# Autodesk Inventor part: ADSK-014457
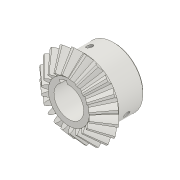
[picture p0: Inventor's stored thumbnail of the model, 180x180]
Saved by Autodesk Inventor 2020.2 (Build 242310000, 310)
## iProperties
CustomPartVersion: 1
Created: 2019-12
Part Number: ADSK-014457
Material: Steel, Mild
Description: Kegelrad1
Document SubType Name: Modeling
Designer: lutzd
Categories: <?xml version="1.0" encoding="UTF-16"?> <MemberInstance><Categories><FamilyTemplate><FamilyTemplateParameter ValueType="xs:double" Id="1" ObjectReferenceKey="da
Mass: 238.264 g
Surface Area: 103.82 cm^2
Volume: 30.3522 cm^3
Density: 7.85 g/cm^3
Appearance: Steel
DocNumber: ADSK-014457
Folder: .
Mass: 0,238 kg
VLT_Material: Stahl, weich
Dimensions: 53,3x33,2x53,3 mm
Title: Kegelrad1
Author: lutzd
Revision Number: -
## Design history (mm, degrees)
node "Oberster Punkt"
node "Netzebene2"
sketch "Skizze des Zahnradkörpers"
  geometry: L1 (0, 0)-(22.879, -27.121); L2 (22.879, -27.121)-(26.768, -23.232); L3 (26.768, -23.232)-(0, 0); L4 (25, -25)-(0, 0); L5 (13.754, -16.305)-(16.093, -13.967); L6 (22.879, -27.121)-(13.754, -16.305); L7 (26.768, -23.232)-(16.093, -13.967); L8 (0, -32.546)-(0, 5.424) reference; L9 (0, -25)-(26.768, -25)
  constraints: 16 end point, 4 point on line, 3 perpendicular, 2 collinear, 1 horizontal alignment, 1 vertical alignment
  dimensions: "d0" = 50 diameter of L4.start L8 (= da_de); "d1" = 45.75736 diameter of L1.end L8 (= da_dfe); "d2" = 53.53553 diameter of L2.end L8 (= da_dae); "d3" = 14.1 distance between parallel lines of L2 L5 (= da_b); "d4" = 23.23223 vertical distance of L2.end L1.start (= da_ve)
revolve "Zahnradkörper" sketch "Skizze des Zahnradkörpers" stored, may be unused: angle "d5" = 90 deg
node "Startpunkt"
node "Zahnebene"
sketch "Startskizze"
  geometry: L1 (0, -43.262)-(0, 12.085) reference; L2 (-1.005, -3.66)-(1.005, -3.66); A1 r 12.943 centre (-13.854, -5.217) between (-1.005, -3.66) and (-4.643, 3.876); A2 r 12.943 centre (13.854, -5.217) between (4.643, 3.876) and (1.005, -3.66); A3 r 39.505 centre (0, -35.355) between (4.643, 3.876) and (-4.643, 3.876); 1 further point
  constraints: 6 point on circle, 3 centre point, 3 symmetric about line, 2 end point, 1 coincident, 1 perpendicular, 1 other
  dimensions: "d7" = 12.94316 radius of A1 (= fd_rr); "d8" = 13.85371 horizontal distance of point (0, -35.355) A1.centre (= fd_x); "d9" = 30.13805 vertical distance of point (0, -35.355) A1.centre (= fd_y); "d57" = 39.50534 radius of A3 (= 0.5 x fd_dva + 0.3 x da_he); "d58" = 31.69534 distance from line of A3.centre L2 (= 0.5 x fd_dva - 1.12 x da_he)
node "Endpunkt"
  node "Endebene"
sketch "Endskizze"
  geometry: L1 (0, -25.672)-(0, 7.171) reference; L2 (-0.596, -2.172)-(0.596, -2.172); A1 r 7.681 centre (-8.221, -3.096) between (-0.596, -2.172) and (-2.755, 2.3); A2 r 7.681 centre (8.221, -3.096) between (2.755, 2.3) and (0.596, -2.172); A3 r 23.443 centre (0, -20.98) between (2.755, 2.3) and (-2.755, 2.3); 1 further point
  constraints: 6 point on circle, 3 centre point, 3 symmetric about line, 2 end point, 1 coincident, 1 other
  dimensions: "d12" = 7.68065 radius of A1 (computed from fd_rr, fd_ratio); "d15" = 8.22098 horizontal distance of A1.centre point (0, -20.98) (computed from fd_x, fd_ratio); "d16" = 17.88433 vertical distance of A1.centre point (0, -20.98) (computed from fd_y, fd_ratio); "d59" = 23.44301 radius of A3 (computed from d57, fd_ratio); "d60" = 18.80845 distance from line of A3.centre L2 (computed from d58, fd_ratio)
feature "Loft" sketch "Endskizze" dims "d17" = 0, "d18" = 90 deg, "d19" = 0, "d20" = 90 deg, "d89" = 0, "da_teethtype" = 0 [user parameter]
sketch "3D-Skizze rechts"
  node "Helical Curve Right" dims "d65" = 244.31626 (computed from da_dm, da_delta, da_beta), "d66" = 31.5, "d67" = 50 (= da_de), "d68" = -45 deg (= -da_delta), "d69" = 10.16466 (computed from fd_loft, da_delta)
node "Endebene rechts"
sketch "Endskizze rechts"
  geometry: L1 (0, -29.736)-(0, 11.235) reference; L2 (-0.596, -2.172)-(0.596, -2.172); A1 r 7.681 centre (-8.221, -3.096) between (-0.596, -2.172) and (-2.755, 2.3); A2 r 7.681 centre (8.221, -3.096) between (2.755, 2.3) and (0.596, -2.172); A3 r 23.443 centre (0, -20.98) between (2.755, 2.3) and (-2.755, 2.3); 1 further point
  constraints: 6 point on circle, 3 centre point, 3 symmetric about line, 2 end point, 1 coincident, 1 perpendicular, 1 other
  dimensions: "d70" = 8.22098 horizontal distance of A3.centre A1.centre (computed from fd_x, fd_ratio); "d71" = 17.88433 vertical distance of point (0, -20.98) A1.centre (computed from fd_y, fd_ratio); "d72" = 7.68065 radius of A1 (computed from fd_rr, fd_ratio); "d73" = 18.80845 distance from line of point (0, -20.98) L2 (computed from d58, fd_ratio); "d74" = 23.44301 radius of A3 (computed from d57, fd_ratio)
feature "Erhebung rechts" sketch "Endskizze rechts" dims "d75" = 0, "d77" = 0, "d79" = 0, "d80" = 90 deg, "d85" = 20, "d92" = 90 deg, "d93" = 90 deg, "da_teethtype" = 0 [user parameter]
sketch "3D-Skizze links"
  node "Helical Curve Left" dims "d26" = 244.31626 (computed from da_dm, da_delta, da_beta), "d27" = 10.16466 (computed from fd_loft, da_delta), "d28" = 50 (= da_de), "d29" = -45 deg (= -da_delta)
node "Endebene links"
sketch "Endskizze links" dims "d56" = 11.379 (derived)
  geometry: L1 (0, -33.95)-(0, 15.174) reference; L2 (-0.596, -2.172)-(0.596, -2.172); A1 r 7.681 centre (-8.221, -3.096) between (-0.596, -2.172) and (-2.755, 2.3); A2 r 7.681 centre (8.221, -3.096) between (2.755, 2.3) and (0.596, -2.172); A3 r 23.443 centre (0, -20.981) between (2.755, 2.3) and (-2.755, 2.3); 2 further points; 1 other entity
  constraints: 6 point on circle, 3 centre point, 3 symmetric about line, 2 end point, 1 coincident, 2 other
  dimensions: "d30" = 7.68065 radius of A1 (computed from fd_rr, fd_ratio); "d31" = 8.22098 horizontal distance of point (0, -20.981) A1.centre (computed from fd_x, fd_ratio); "d32" = 17.88433 vertical distance of A1.centre point (0, -20.981) (computed from fd_y, fd_ratio); "d61" = 23.44301 radius of A3 (computed from d57, fd_ratio); "d62" = 18.80845 distance from line of point (0, -20.981) L2 (computed from d58, fd_ratio)
feature "Erhebung links" sketch "Endskizze links" dims "d35" = 0, "d37" = 0, "d39" = 0, "d40" = 90 deg, "d84" = 10, "d90" = 90 deg, "d91" = 90 deg, "da_teethtype" = 0 [user parameter]
sketch "Körperskizze"
  geometry: L1 (0, -29.285)-(0, -14.142) reference; L2 (22.879, -27.121)-(13.754, -16.305) reference; L3 (13.754, -16.305)-(0, -16.305); L4 (22.879, -27.121)-(0, -27.121)
  constraints: 4 end point, 2 perpendicular, 2 point on line
revolve "Festkörper" sketch "Körperskizze" stored, may be unused: angle "d46" = 90 deg
sketch "Sketch6"
  geometry: L1 (25, -25)-(0, 0) reference; L2 (0, -30)-(0, 5) reference
feature "Flankendurchmesser" sketch "Sketch6" dims angle "d47" = 90 deg
sketch "Skizze8"
  geometry: C1 r 20 at (0, 0); 1 further point
  constraints: 1 centre point, 1 coincident
  dimensions: "d94" = 40 diameter of C1
extrude "Extrusion1" join sketch "Skizze8" distance "d95" = 20; taper "d96" = 0 deg
feature "Nabenkeilnut"
workplane "Arbeitsebene7"
  workplane "Arbeitsebene6"
workplane "Arbeitsebene8"
sketch "Skizze9"
  geometry: L1 (-20, -20)-(20, -20) reference; L2 (0, -29.424)-(0, 36.546) reference; 2 further points
  constraints: 1 point on line
  dimensions: "d98" = 10 distance from line of point (0, -10) L1
hole "Bohrung1" sketch "Skizze9" at (0, -10) diameter "d99" = 4.134; stored, may be unused: countersink angle "d103" = 90 deg, drill point angle "d105" = 118 deg; dims "d100" = 10, "d101" = 4, "d102" = 2, "d104" = 8
workplane "Arbeitsebene10"
  workplane "Arbeitsebene9"
sketch "Skizze10"
  geometry: L1 (0, -29.424)-(0, 36.546) reference; L2 (-20, -20)-(20, -20) reference; 2 further points
  constraints: 1 point on line
  dimensions: "d107" = 10 distance from line of L2 point (0, -10)
hole "Bohrung2" sketch "Skizze10" at (0, -10) diameter "d108" = 4.134; stored, may be unused: countersink angle "d112" = 90 deg, drill point angle "d114" = 118 deg; dims "d109" = 10, "d110" = 4, "d111" = 2, "d113" = 8
chamfer "Fase1" distance "d115" = 1; stored, may be unused: second distance "d116" = 2, angle "d117" = 45 deg
body "Solid1"
pattern_circular "Circular Pattern" dims angle "d22" = 360 deg, "d88" = 0, "da_teethtype" = 0 [user parameter]
pattern_circular "Runde Anordnung rechts" dims angle "d82" = 360 deg, "da_teethtype" = 0 [user parameter]
pattern_circular "Runde Anordnung links" dims angle "d42" = 360 deg, "da_teethtype" = 0 [user parameter]
body "Srf1"
other parameters: "da_b" = 14.1 [user parameter; used in 2 equation terms], "da_de" = 50 [user parameter; used in 4 equation terms], "da_dae" = 53.53553 [user parameter; used in 2 equation terms], "da_dfe" = 45.75736 [user parameter; used in 1 equation term], "da_le" = 35.35534 [user parameter; used in 1 equation term], "da_omega" = 90 deg [user parameter; used in 1 equation term], "da_beta" = 0 [user parameter; used in 2 equation terms], "da_delta" = 45 deg [user parameter; used in 8 equation terms], "da_alpha" = 20 deg [user parameter; used in 2 equation terms], "da_he" = 5.5 [user parameter; used in 4 equation terms], "da_ve" = 23.23223 [user parameter; used in 1 equation term], "fd_dv" = 70.71068 (computed from da_de, da_delta) [user parameter; used in 1 equation term], "fd_dva" = 75.71068 (computed from da_dae, da_delta) [user parameter; used in 3 equation terms], "fd_dvb" = 66.4463 (computed from fd_dv, da_alpha) [user parameter; used in 2 equation terms], "da_zv" = 282.84271 [user parameter; used in 1 equation term], "fd_loft" = 14.375 (= da_b + 0.05 x da_he) [user parameter; used in 4 equation terms], "fd_ratio" = 5.93414 (computed from da_le, fd_loft) [user parameter; used in 15 equation terms], "fd_rr" = 12.94316 (computed from fd_dd, fd_dvb) [user parameter; used in 6 equation terms], "fd_angle" = 0.56153 (computed from da_zv) [user parameter; used in 4 equation terms], "fd_x1" = 1.98427 (computed from da_dvw, fd_angle) [user parameter; used in 1 equation term], "fd_y1" = 35.29961 (computed from da_dvw, fd_angle) [user parameter; used in 1 equation term], "fd_x2" = 11.86944 (computed from fd_rr, fd_angle2, fd_angle) [user parameter; used in 1 equation term], "fd_y2" = 5.16156 (computed from fd_rr, fd_angle2, fd_angle) [user parameter; used in 1 equation term], "fd_x" = 13.85371 (= fd_x1 + fd_x2) [user parameter; used in 4 equation terms], "fd_y" = 30.13805 (= fd_y1 - fd_y2) [user parameter; used in 4 equation terms], "fd_angle2" = 3.5404 (computed from fd_dvb, fd_dd, da_alpha) [user parameter; used in 2 equation terms], "fd_dd" = 71.31068 (= fd_dva - 0.8 x da_he) [user parameter; used in 2 equation terms], "da_dvw" = 70.71068 [user parameter; used in 2 equation terms], "d11" = 14.375 (= fd_loft), "da_dm" = 40.02979 [user parameter; used in 2 equation terms], "da_x" = 0 [user parameter], "da_m" = 2.5 [user parameter], "d48" = 0, "d49" = 0, "d50" = 90 deg (= da_omega), "d51" = 9 deg (computed from da_z), "d52" = 0, "d53" = 0, "d54" = 0, "d97" = 90 deg, "d106" = 45 deg
